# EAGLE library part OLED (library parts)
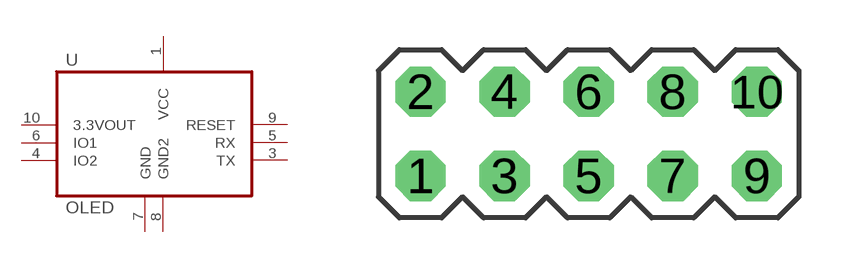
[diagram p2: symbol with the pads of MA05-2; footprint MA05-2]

Designator prefix -

## OLED  [MA05-2]
1  VCC  pas
3  TX  pas
4  IO2  pas
5  RX  pas
6  IO1  pas
7  GND  pas
8  GND2  pas
9  RESET  pas
10  3.3VOUT  pas

## Footprint MA05-2 (pad centres in mm)
PIN HEADER
drill 1.016 octagon: 1 -5.08,-1.27; 2 -5.08,1.27; 3 -2.54,-1.27; 4 -2.54,1.27; 5 0,-1.27; 6 0,1.27; 7 2.54,-1.27; 8 2.54,1.27; 9 5.08,-1.27; 10 5.08,1.27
